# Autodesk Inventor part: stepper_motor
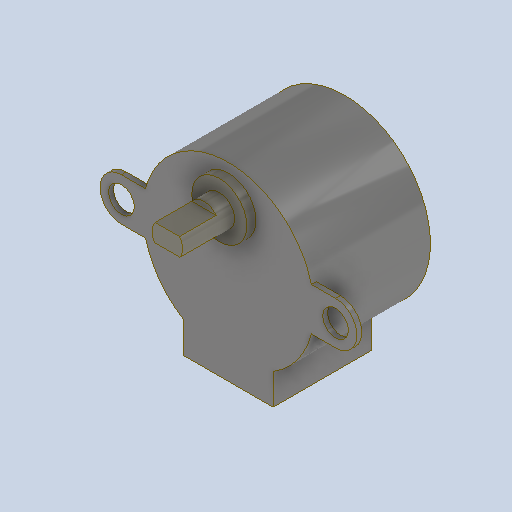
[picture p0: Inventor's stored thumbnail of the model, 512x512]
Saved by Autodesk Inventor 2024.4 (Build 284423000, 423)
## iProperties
Created: 2025-07
Part Number: stepper_motor
Material: Generic
Document SubType Name: Modeling
Designer: AdminForWorker
Density: 1 g/cm^3
Appearance: Default
Title: stepper_motor v2
Author: AdminForWorker
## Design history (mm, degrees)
feature "Body1"
body "Solid1"
